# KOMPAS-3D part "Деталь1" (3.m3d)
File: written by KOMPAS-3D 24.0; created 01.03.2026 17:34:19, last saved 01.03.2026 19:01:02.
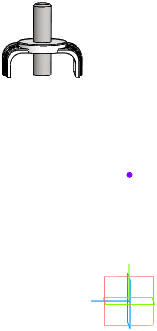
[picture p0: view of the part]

Document properties: Автор: R2D2; Полное имя файла: E:\Работа\Зайцев\GVWR3131M-2W-F-S Задвижка клиновая с выдвижным штоком DN.ru Ду50-200 Ру63\DN50\исходные материалы\3.m3d

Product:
- Body: Твердое тело1  | qty 1
    Масса: 0.395685
- Part/product: Деталь1
    Масса: 0.395685
    additional columns: Типовые

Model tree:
1. Твердое тело1  (labels: Твердое тело1)
2. Точка:1
     Y = 130.5; Координата Y = 130.5
3. Эскиз:1
4. Элемент выдавливания:1
     Расстояние 1 = 500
